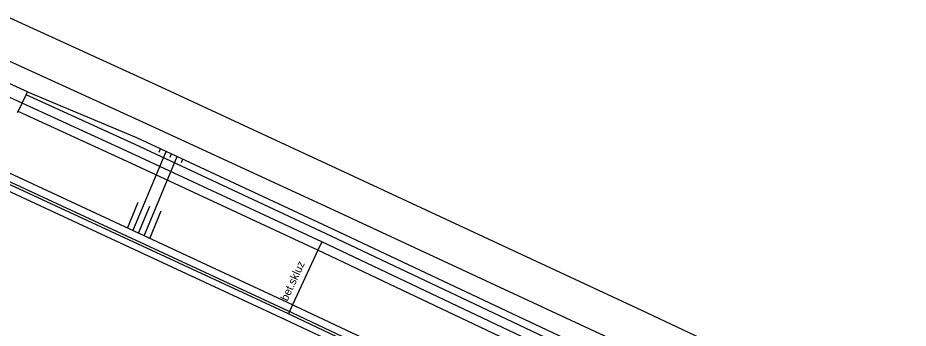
# Model space of a CAD drawing. Extents: x -539244 to -537359, y -1183785 to -1181851.
# Drawn here: x -538727 to -538654.7, y -1182697.4 to -1182672.2 of the extents above; entities that cross this region are included whole.
import ezdxf

# ---------------------------------------------------------------- set-up
doc = ezdxf.new("R2010")
doc.units = 0
for name, color, linetype in [('Vrstva 10', 7, 'Continuous'), ('Vrstva 11', 7, 'Continuous'), ('Vrstva 14', 7, 'Continuous'), ('Vrstva 15', 7, 'Continuous'), ('Vrstva 40', 7, 'Continuous'), ('Vrstva 9', 7, 'Continuous')]:
    doc.layers.add(name, color=color, linetype=linetype)

msp = doc.modelspace()

# ---------------------------------------------------------------- linework, layer by layer
at = {"layer": 'Vrstva 10'}
for p, q in [((-538741.879, -1182679.738), (-538705.317, -1182696.682)), ((-538705.317, -1182696.682), (-538687.201, -1182705.191))]:
    msp.add_line(p, q, dxfattribs=at)
at = {"layer": 'Vrstva 11'}
for p, q in [((-538727.676, -1182672.216), (-538715.774, -1182677.646)), ((-538726.251, -1182678.233), (-538732.242, -1182675.467)), ((-538716.891, -1182680.69), (-538728.795, -1182675.242)), ((-538715.774, -1182677.646), (-538700.125, -1182684.892)), ((-538717.512, -1182682.506), (-538726.362, -1182678.464)), ((-538718.14, -1182683.868), (-538727.013, -1182679.815)), ((-538701.299, -1182687.859), (-538716.891, -1182680.69)), ((-538702.029, -1182689.71), (-538717.512, -1182682.506)), ((-538702.661, -1182691.07), (-538718.14, -1182683.868)), ((-538700.125, -1182684.892), (-538676.387, -1182695.934)), ((-538677.484, -1182698.903), (-538701.299, -1182687.859)), ((-538678.298, -1182700.924), (-538702.029, -1182689.71)), ((-538678.942, -1182702.28), (-538702.661, -1182691.07)), ((-538687.038, -1182704.724), (-538704.782, -1182696.357)), ((-538676.387, -1182695.934), (-538654.715, -1182706.071))]:
    msp.add_line(p, q, dxfattribs=at)
for points in [[(-538727.053, -1182679.899), (-538727.013, -1182679.815), (-538726.669, -1182679.148), (-538726.362, -1182678.464), (-538726.251, -1182678.233)], [(-538704.782, -1182696.357), (-538705.043, -1182696.236), (-538741.697, -1182679.269)]]:
    msp.add_lwpolyline(points, dxfattribs=at)
at = {"layer": 'Vrstva 14'}
for p, q in [((-538726.669, -1182679.148), (-538729.788, -1182677.73)), ((-538726.251, -1182678.233), (-538717.405, -1182681.925)), ((-538717.826, -1182683.187), (-538726.669, -1182679.148)), ((-538717.405, -1182681.925), (-538701.882, -1182689.158)), ((-538702.347, -1182690.389), (-538717.826, -1182683.187)), ((-538701.882, -1182689.158), (-538678.035, -1182700.353)), ((-538702.347, -1182690.389), (-538702.661, -1182691.07)), ((-538678.62, -1182701.602), (-538702.347, -1182690.389)), ((-538702.661, -1182691.07), (-538704.71, -1182695.513)), ((-538704.71, -1182695.513), (-538705.043, -1182696.236)), ((-538686.751, -1182703.933), (-538704.454, -1182695.633))]:
    msp.add_line(p, q, dxfattribs=at)
msp.add_lwpolyline([(-538704.454, -1182695.633), (-538704.71, -1182695.513), (-538741.401, -1182678.466)], dxfattribs=at)
at = {"layer": 'Vrstva 15'}
for p, q in [((-538717.682, -1182689.487), (-538714.991, -1182683.05)), ((-538716.775, -1182689.908), (-538714.085, -1182683.472)), ((-538715.562, -1182683.116), (-538715.446, -1182682.838)), ((-538714.648, -1182683.525), (-538714.538, -1182683.261)), ((-538713.74, -1182683.944), (-538713.631, -1182683.684)), ((-538718.137, -1182689.276), (-538717.256, -1182687.169)), ((-538717.229, -1182689.697), (-538716.307, -1182687.492)), ((-538716.321, -1182690.119), (-538715.388, -1182687.887))]:
    msp.add_line(p, q, dxfattribs=at)
at = {"layer": 'Vrstva 9'}
for p, q in [((-538704.698, -1182696.176), (-538741.613, -1182679.088)), ((-538686.953, -1182704.543), (-538704.697, -1182696.176))]:
    msp.add_line(p, q, dxfattribs=at)

# ---------------------------------------------------------------- texts
at = {"layer": 'Vrstva 40'}
msp.add_text('bet.skluz', height=0.65, rotation=65.24599, dxfattribs=at).set_placement((-538705.139, -1182695.252))

doc.saveas('drawing.dxf')
